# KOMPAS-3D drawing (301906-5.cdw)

Views: Вид 1, Вид 2, Вид Д, Вид 4
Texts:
  Корпус
  денис
  Текст на чертеже
  Размерные надписи
  Шероховатость
  Линия-выноска #1
  Линия-выноска #2
  Линия-выноска #3
  Отклонения формы и база
  Заголовок таблицы
  Ячейка таблицы
  Стрелка вида
  Обозначение изменения
  Фигурная скобка
  Номер узла
  Марка координационной оси
  VRCB
  Выносная надпись
  Обозначение узла
  Марка/позиционное обозначение с линией-выноской
  Марка/позиционное обозначение на линии
  Марка/позиционное обозначение без линии-выноски
  ГОСТ 5264-80-Т6
  ГОСТ 5264-80-Н1  12
  ГОСТ 5264-80-С15
  ГОСТ 5264-80-С42
  ГОСТ 5264-80-Т7  12
  ГОСТ 5264-80-Т7  20
  Технические требования
  1. После сварки неровности зачистить с плавным переходом к основному металлу.
  2. Сварные швы подлежат контролю качества соединений
  3. Аппарат покрасить после окончательной обработки и сборки. Красить только черный металл
  Баранов ДА.
  СПбГТИ(ТУ)
  гр.364
Dimensions and other numbers on the sheet: 105.16.01.00.000СБ; 7; 800; 750; 4365,72; 3146; 2400; 1120; 79,03; 392,81; 319,15; 1629,75; 3256; 4; 3; 6; 5; 1; 8; 9; 10; 11; 13; 21; 15; 23; 14; 22; 16; 24; 17; 25; 18; 26; 19; 27; 2; 28; 29; 4 отв; 150; 1:15; 105.16.02.00.000СБ-; 4231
